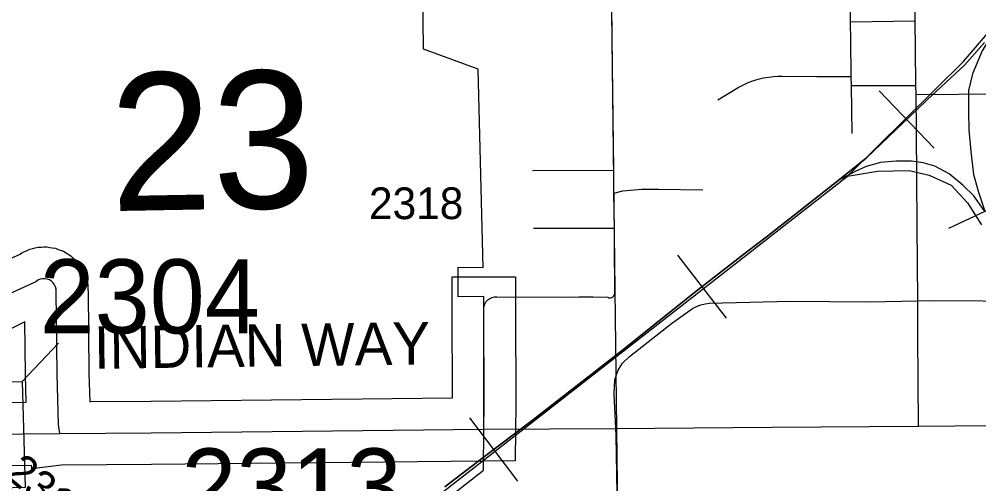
# Model space of a CAD drawing. Extents: x 23.6 to 68.7, y -63 to -29.
# Drawn here: x 43.146 to 44.053, y -49.145 to -48.705 of the extents above; entities that cross this region are included whole.
import ezdxf

# ---------------------------------------------------------------- set-up
doc = ezdxf.new("R2010")
doc.units = 0
for name, color, linetype in [('tdCoCityStreetMajor', 7, 'Continuous'), ('tdCoCityStreetMinor', 7, 'Continuous'), ('tdCoCorpBndry', 7, 'Continuous'), ('tdCoRRCL', 7, 'Continuous'), ('tdCoSecRdNmbr', 7, 'Continuous'), ('tdCoSecRdTxt', 7, 'Continuous'), ('tdCoSecRteBand', 7, 'Continuous'), ('tdCoSecRteCL', 7, 'Continuous'), ('tdCoSectLine', 7, 'Continuous'), ('tdCoSectNmbr', 7, 'Continuous'), ('tdCoStrucNonDivPri', 7, 'Continuous'), ('tdCoSurfAsphalt', 7, 'Continuous'), ('tdCoSurfConc', 7, 'Continuous'), ('tdCoSurfGravel', 7, 'Continuous')]:
    doc.layers.add(name, color=color, linetype=linetype)

msp = doc.modelspace()

# ---------------------------------------------------------------- linework, layer by layer
at = {"layer": 'tdCoCityStreetMajor'}
for points in [[(43.5852, -48.97867), (43.58547, -48.97655), (43.58621, -48.97435), (43.58739, -48.97235), (43.58895, -48.97063), (43.59082, -48.96927), (43.59293, -48.96831), (43.59519, -48.9678), (43.59751, -48.96775), (43.66138, -48.968), (43.67503, -48.96786), (43.68868, -48.96794), (43.70232, -48.96825), (43.70353, -48.96873), (43.70483, -48.96884), (43.70611, -48.96857), (43.70725, -48.96794), (43.70817, -48.96702), (43.70878, -48.96586), (43.70903, -48.96459), (43.70878, -48.91576), (43.70863, -48.90277), (43.70824, -48.86999), (43.70798, -48.84802), (43.70681, -48.74954), (43.70558, -48.63561)], [(43.58518, -49.09303), (43.71012, -49.09216), (43.85768, -49.09114), (43.99627, -49.09001), (44.10059, -49.08916), (44.11949, -49.08896)]]:
    msp.add_lwpolyline(points, dxfattribs=at)
at = {"layer": 'tdCoCityStreetMinor'}
for p, q in [((43.93199, -48.70784), (43.99326, -48.70699)), ((43.93286, -48.76811), (43.93271, -48.75956)), ((43.93286, -48.76811), (43.99389, -48.76809)), ((43.93362, -48.81333), (43.93286, -48.76811)), ((43.99397, -48.77653), (43.99389, -48.76809)), ((43.99397, -48.77653), (44.11275, -48.77551)), ((43.63127, -48.84853), (43.70798, -48.84802)), ((43.63201, -48.90303), (43.70863, -48.90277))]:
    msp.add_line(p, q, dxfattribs=at)
for points in [[(43.93199, -48.70784), (43.9316, -48.6618), (43.93147, -48.64643)], [(43.99326, -48.70699), (43.99282, -48.66777), (43.99262, -48.64621)], [(43.93271, -48.75956), (43.93214, -48.72553), (43.93199, -48.70784)], [(43.99389, -48.76809), (43.99356, -48.73361), (43.99326, -48.70699)], [(43.80632, -48.7816), (43.8256, -48.77004), (43.82998, -48.76776), (43.83506, -48.7653), (43.84049, -48.76338), (43.8447, -48.76197), (43.84971, -48.76097), (43.85462, -48.76004), (43.85922, -48.75968), (43.86324, -48.75938), (43.86775, -48.75926), (43.90023, -48.75941), (43.93271, -48.75956)], [(43.99555, -48.97148), (43.99504, -48.90032), (43.9943, -48.81178), (43.99397, -48.77653)], [(43.70824, -48.86999), (43.7166, -48.86752), (43.73435, -48.86604), (43.75038, -48.86604), (43.79231, -48.86678)], [(43.71288, -49.31266), (43.71249, -49.25954), (43.71139, -49.15334), (43.71047, -49.09887), (43.71012, -49.09216), (43.70845, -49.05962), (43.70918, -49.04641), (43.71037, -49.04264), (43.71212, -49.03706), (43.71634, -49.03045), (43.72294, -49.02422), (43.76274, -48.99304), (43.78255, -48.97873), (43.78631, -48.97685), (43.79026, -48.97538), (43.79434, -48.97436), (43.79851, -48.97378), (43.87481, -48.97194), (43.95001, -48.97249), (43.99555, -48.97148)], [(43.99555, -48.97148), (44.00779, -48.97121), (44.10665, -48.97194), (44.11657, -48.97159)], [(43.99627, -49.09001), (43.99578, -49.00438), (43.99555, -48.97148)]]:
    msp.add_lwpolyline(points, dxfattribs=at)
at = {"layer": 'tdCoCorpBndry'}
msp.add_lwpolyline([(43.29838, -49.35629), (43.58497, -49.1318), (43.58518, -49.09303), (43.58518, -48.97885), (43.58522, -48.96745), (43.56084, -48.9677), (43.56091, -48.9398), (43.58446, -48.94006), (43.57993, -48.75264), (43.52821, -48.73361), (43.52666, -48.59571), (43.57613, -48.59525), (43.5808, -48.59518), (43.58045, -48.52807), (43.44428, -48.52984), (43.40868, -48.59482), (43.40759, -48.59682), (43.36411, -48.59733), (43.01992, -48.60188)], dxfattribs=at)
at = {"layer": 'tdCoRRCL'}
for p, q in [((44.01103, -48.82723), (43.95912, -48.77309)), ((44.02494, -48.9029), (44.09281, -48.87097)), ((43.81458, -48.98784), (43.76867, -48.92854)), ((43.61721, -49.14197), (43.57198, -49.08214))]:
    msp.add_line(p, q, dxfattribs=at)
for points in [[(42.74649, -50.31687), (42.74164, -50.05586), (42.75629, -49.92628), (42.79153, -49.80443), (42.85538, -49.70442), (42.92256, -49.6249), (42.97285, -49.5992), (43.92922, -48.85362), (44.03877, -48.74532), (44.06896, -48.71007), (44.09338, -48.67223), (44.10531, -48.65074), (44.10984, -48.63845), (44.1114, -48.63233), (44.11198, -48.62671), (44.11322, -48.05326), (44.10862, -47.52765), (44.11109, -47.4487), (44.10535, -47.15357), (44.11332, -46.467), (44.17329, -45.46369)], [(44.07316, -48.70716), (44.05653, -48.73543), (44.04736, -48.75718), (44.04369, -48.77291), (44.04342, -48.79284), (44.04395, -48.80988), (44.04578, -48.83032), (44.04841, -48.85208), (44.05312, -48.86886), (44.05888, -48.88694), (44.0585, -48.88613), (44.04854, -48.87224), (44.03831, -48.86228), (44.02521, -48.85153), (44.01184, -48.84445), (44.00083, -48.84131), (43.98955, -48.83947), (43.97514, -48.83947), (43.96019, -48.84078), (43.94683, -48.84471), (43.93582, -48.8497), (43.91984, -48.85804)], [(44.05876, -48.72728), (44.03989, -48.74877), (44.0045, -48.78154), (44.00279, -48.78318), (43.94709, -48.83659), (43.91984, -48.85804), (43.85219, -48.9113), (43.83398, -48.9254), (43.78718, -48.96163), (43.71352, -49.02035), (43.63095, -49.08457), (43.58466, -49.11957), (43.54834, -49.14735)], [(43.54834, -49.14735), (43.58466, -49.11957), (43.63095, -49.08457), (43.71352, -49.02035), (43.78718, -48.96163), (43.83398, -48.9254), (43.85219, -48.9113), (43.91984, -48.85804), (43.94709, -48.83659), (44.00279, -48.78318), (44.0045, -48.78154), (44.03989, -48.74877), (44.05876, -48.72728)], [(43.92922, -48.85362), (43.95754, -48.84906), (43.98758, -48.84837), (44.00632, -48.85269), (44.02716, -48.86223), (44.04264, -48.87886), (44.05591, -48.89986)]]:
    msp.add_lwpolyline(points, dxfattribs=at)
at = {"layer": 'tdCoSecRteBand'}
for points in [[(43.12746, -48.93606), (43.14656, -48.92737), (43.14847, -48.92602), (43.15113, -48.92483), (43.1532, -48.9239), (43.15587, -48.9227), (43.15872, -48.92204), (43.16092, -48.92154), (43.16377, -48.92088), (43.16669, -48.92078), (43.16895, -48.92071), (43.17188, -48.92061), (43.17476, -48.92108), (43.17699, -48.92144), (43.17988, -48.92191), (43.18262, -48.92293), (43.18474, -48.92372), (43.18748, -48.92474), (43.18998, -48.92627), (43.1919, -48.92746), (43.1944, -48.92899), (43.19655, -48.93097), (43.19821, -48.9325), (43.20036, -48.93449), (43.20209, -48.93685), (43.20342, -48.93867), (43.20515, -48.94103), (43.20639, -48.94369), (43.20734, -48.94573), (43.20858, -48.94839), (43.20928, -48.95123), (43.20982, -48.95342), (43.21053, -48.95626), (43.21067, -48.95918), (43.21077, -48.96144), (43.2108, -48.96201), (43.21081, -48.96259), (43.21154, -49.04019), (43.21237, -49.06684), (43.21373, -49.06682), (43.27022, -49.06632), (43.55541, -49.06334), (43.55518, -48.97893), (43.5551, -48.94893), (43.6151, -48.94877), (43.61518, -48.97877), (43.61543, -49.07001), (43.61543, -49.07022), (43.61543, -49.07042), (43.61518, -49.09335), (43.61486, -49.12272), (43.58549, -49.12303), (43.27082, -49.12631), (43.2708, -49.12631), (43.27078, -49.12631), (43.18582, -49.12708), (43.15755, -49.13026), (43.15722, -49.12733), (43.07895, -49.12804)], [(43.07814, -49.06804), (43.15236, -49.06738), (43.15156, -49.04173), (43.15155, -49.04141), (43.15155, -49.04109), (43.15108, -48.99131), (43.13652, -48.99858)]]:
    msp.add_lwpolyline(points, dxfattribs=at)
at = {"layer": 'tdCoSecRteCL'}
for points in [[(43.18401, -49.09709), (43.18303, -49.0884), (43.18155, -49.0408), (43.18081, -48.96287), (43.1807, -48.96062), (43.18016, -48.95842), (43.1792, -48.95638), (43.17787, -48.95455), (43.17621, -48.95302), (43.17428, -48.95184), (43.17217, -48.95105), (43.16994, -48.95069), (43.16768, -48.95076), (43.16548, -48.95127), (43.16342, -48.9522), (43.16157, -48.9535), (43.13987, -48.96337), (43.1231, -48.97175), (43.11842, -48.97372), (43.11422, -48.97496), (43.08192, -48.97545), (43.03765, -48.97594), (43.01583, -48.97668)], [(43.18401, -49.09709), (43.27051, -49.09632), (43.58518, -49.09303), (43.58543, -49.07009), (43.58518, -48.97885)], [(42.96521, -49.10149), (42.99776, -49.10026), (43.02844, -49.09942), (43.04992, -49.09883), (43.0784, -49.09804), (43.18401, -49.09709)]]:
    msp.add_lwpolyline(points, dxfattribs=at)
at = {"layer": 'tdCoSectLine'}
msp.add_lwpolyline([(43.7047, -48.59338), (43.71668, -49.59097)], dxfattribs=at)
at = {"layer": 'tdCoStrucNonDivPri'}
msp.add_line((43.14858, -49.04798), (43.18295, -49.01166), dxfattribs=at)
msp.add_lwpolyline([(42.92697, -49.05408), (43.14858, -49.04798), (43.15133, -49.14794), (42.92972, -49.15404)], close=True, dxfattribs=at)
at = {"layer": 'tdCoSurfAsphalt'}
msp.add_lwpolyline([(43.58518, -49.09303), (43.58543, -49.07009), (43.58518, -48.97885)], dxfattribs=at)
at = {"layer": 'tdCoSurfConc'}
msp.add_lwpolyline([(42.96521, -49.10149), (42.99776, -49.10026), (43.02844, -49.09942), (43.04992, -49.09883), (43.0784, -49.09804), (43.18401, -49.09709), (43.27051, -49.09632), (43.58518, -49.09303)], dxfattribs=at)
at = {"layer": 'tdCoSurfGravel'}
msp.add_lwpolyline([(43.18401, -49.09709), (43.18303, -49.0884), (43.18155, -49.0408), (43.18081, -48.96287), (43.1807, -48.96062), (43.18016, -48.95842), (43.1792, -48.95638), (43.17787, -48.95455), (43.17621, -48.95302), (43.17428, -48.95184), (43.17217, -48.95105), (43.16994, -48.95069), (43.16768, -48.95076), (43.16548, -48.95127), (43.16342, -48.9522), (43.16157, -48.9535), (43.13987, -48.96337), (43.1231, -48.97175), (43.11842, -48.97372), (43.11422, -48.97496), (43.08192, -48.97545), (43.03765, -48.97594), (43.01583, -48.97668)], dxfattribs=at)

# ---------------------------------------------------------------- texts
at = {"layer": 'tdCoSecRdNmbr'}
for s, height, rotation, p in [('2318', 0.03, 0.03346, (43.47654, -48.89441)), ('2304', 0.07, 0.03373, (43.16502, -49.00239)), ('2313', 0.07, 0.03383, (43.2992, -49.18122)), ('2311', 0.03, 320.03362, (43.13072, -49.13676))]:
    msp.add_text(s, height=height, rotation=rotation, dxfattribs=at).set_placement(p)
at = {"layer": 'tdCoSecRdTxt'}
msp.add_text('INDIAN WAY', height=0.04, rotation=0.77077, dxfattribs=at).set_placement((43.21659, -49.03589))
at = {"layer": 'tdCoSectNmbr'}
msp.add_text('23', height=0.13, rotation=1.03371, dxfattribs=at).set_placement((43.23258, -48.88681))

doc.saveas('drawing.dxf')
